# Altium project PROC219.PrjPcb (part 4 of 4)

## Sheet PROC219_Hardware.SchDoc
size 431 x 279 mm; Date: Not shown in title block; ApprovedBy: Not shown in title block; CheckedBy: Not shown in title block; Author: Not shown in title block; CompanyName: Not shown in title block; Engineer: Not shown in title block; Organization: Not shown in title block; Address1: Not shown in title block; Address2: Not shown in title block; Address3: Not shown in title block; Address4: Not shown in title block; DocumentNumber: 3; Revision: Use project parameter SCH_Rev; SheetNumber: 16; SheetTotal: 16; PageSetup: Record=PageOptions¦CenterHorizontal=True¦CenterVertical=True¦PrintScale=1.00¦XCorrection=1.00¦YCorrection=1.00¦PrintKind=0¦BorderSize=5000000¦LeftOffset=0¦BottomOffset=0¦Orientation=2¦PaperLength=1000¦PaperWidth=1000¦Scale=100¦PaperSource=15¦PrintQuality=600¦MediaType=1¦DitherType=10¦PaperKind=Letter¦PrintScaleMode=1
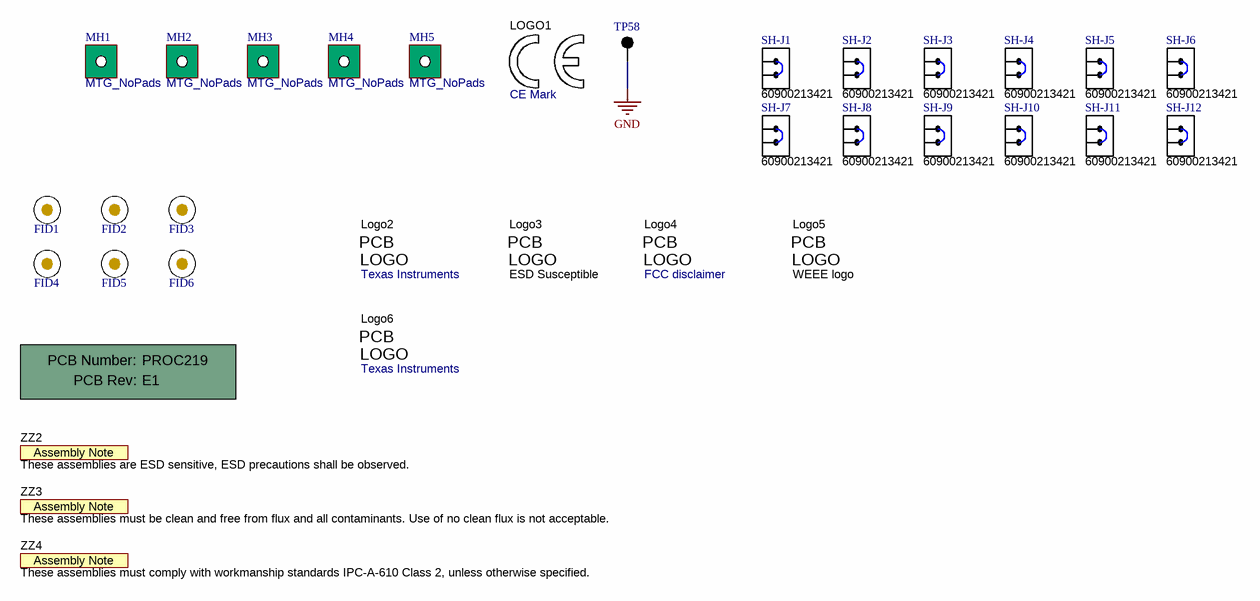
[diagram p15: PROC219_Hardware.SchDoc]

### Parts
!PCB1  Printed Circuit Board  (value not drawn)  (mechanical)
FID1  Fiducial  [Fiducial10-20]  (value not drawn)  (no BOM)
FID2  Fiducial  [Fiducial10-20]  (value not drawn)  (no BOM)
FID3  Fiducial  [Fiducial10-20]  (value not drawn)  (no BOM)
FID4  Fiducial  [Fiducial10-20]  (value not drawn)  (no BOM)
FID5  Fiducial  [Fiducial10-20]  (value not drawn)  (no BOM)
FID6  Fiducial  [Fiducial10-20]  (value not drawn)  (no BOM)
LOGO1  CE Mark  [CE_Mark_5mm]  (no BOM)
Logo2  Texas Instruments  [TI_Horizontal_Overlay_Medium]  (no BOM)
Logo3  ESD Susceptible  [ESD_Overlay_Large]  (no BOM)
Logo4  FCC disclaimer  [FCC_disclaimer]  (no BOM)
Logo5  WEEE logo  [WEEE_Minimum]  (no BOM)
Logo6  Texas Instruments  [TI_Horizontal_Overlay_Medium]  (no BOM)
MH1  MTG_NoPads  [NPTH125mil]  (no BOM)
MH2  MTG_NoPads  [NPTH125mil]  (no BOM)
MH3  MTG_NoPads  [NPTH125mil]  (no BOM)
MH4  MTG_NoPads  [NPTH125mil]  (no BOM)
MH5  MTG_NoPads  [NPTH125mil]  (no BOM)
SH-J1  60900213421  [Wurth_60900213421]
SH-J2  60900213421  [Wurth_60900213421]
SH-J3  60900213421  [Wurth_60900213421]
SH-J4  60900213421  [Wurth_60900213421]
SH-J5  60900213421  [Wurth_60900213421]
SH-J6  60900213421  [Wurth_60900213421]
SH-J7  60900213421  [Wurth_60900213421]
SH-J8  60900213421  [Wurth_60900213421]
SH-J9  60900213421  [Wurth_60900213421]
SH-J10  60900213421  [Wurth_60900213421]
SH-J11  60900213421  [Wurth_60900213421]
SH-J12  60900213421  [Wurth_60900213421]
TP58  5011  [Keystone5011]  (value not drawn)
ZZ2  These assemblies are ESD sensitive, ESD precautions shall be observed.  [AssemblyNote]  (no BOM)
ZZ3  These assemblies must be clean and free from flux and all contaminants. Use of no clean flux is not acceptable.  [AssemblyNote]  (no BOM)
ZZ4  These assemblies must comply with workmanship standards IPC-A-610 Class 2, unless otherwise specified.  [AssemblyNote]  (no BOM)

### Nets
GND: TP58.1

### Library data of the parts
!PCB1 = CMP-0003618-2: Manufacturer: Any; PartNumber: PROC219
FID1-FID6 = CMP-0077181-1: Fiducial mark.  There is nothing to buy or mount.
LOGO1 = CMP-0074844-1: SymbolCreator: a0412235
Logo2 Logo6 = CMP-0074838-1: Texas Instrument Corporate Signature; SymbolCreator: a0412235; Lib Reference: TI_Logo
Logo3 = CMP-0074840-1: ESD Susceptible Symbol; SymbolCreator: a0412235; Lib Reference: ESD_Susceptible
Logo4 = CMP-0074847-1: FCC_disclaimer
Logo5 = CMP-0074769-4: Manufacturer: Texas Instruments; CompType: IC; AEC Category: Q200
MH1-MH5 = CMP-0078424-2: PCB Mounting Hole, No Pad; Manufacturer: Any; Key: Mounting Hole (non-standard) No Pad
SH-J1-SH-J12 = CMP-0003761-2: Shunt, 2.54mm, Gold, Black; Manufacturer: Wurth Elektronik
TP58 = CMP-0055148-2: Test Point, Multipurpose, Black, TH; Manufacturer: Keystone Electronics; CNHeader: FALSE; ContactFinish: Silver; Green_REACh: Passed; Green_Lifecycle: Active; CT: TRUE
ZZ2 = CMP-0077236-1
ZZ3 = CMP-0077237-1
ZZ4 = CMP-0077238-1

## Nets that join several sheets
3.3V: PROC219_Power_IN_Dig (5 pins), PROC219_MSPM0 (9 pins), PROC219_PLC (19 pins), PROC219_Pilot_Interface (R60.2 R64.2 R66.2 SW1.5), PROC219_GBT (SW2.5), PROC219_CHAdeMO (6 pins), PROC219_PluckLock (7 pins), PROC219_Temp_Sense (R121.2 R122.2), PROC219_Serial (9 pins), PROC219_CAN (8 pins), PROC219_IO (6 pins), PROC219_XDS110_Debug (32 pins), PROC219_Connectors (7 pins)
5V: PROC219_Power_IN_Dig (7 pins), PROC219_Power_Analog (L7.1), PROC219_CAN (C135.1 C140.1 U21.3 U23.3), PROC219_IO (R145.1 R149.1), PROC219_Connectors (J26.5)
12V: PROC219_Power_IN_Dig (7 pins), PROC219_CHAdeMO (6 pins), PROC219_PluckLock (F1.2 J14.2), PROC219_IO (R148.2), PROC219_Connectors (J30.1)
+12V_EXT: PROC219_Power_IN_Dig (R3.2), PROC219_Connectors (J26.1 J26.2)
+12Va: PROC219_Power_Analog (7 pins), PROC219_Pilot_Interface (C90.2 R70.1 U10.6), PROC219_GBT (8 pins)
+14V_EXT: PROC219_Power_Analog (6 pins), PROC219_Connectors (J26.3)
-12Va: PROC219_Power_Analog (7 pins), PROC219_Pilot_Interface (C92.2 U10.2 U10.5)
-14V_EXT: PROC219_Power_Analog (5 pins), PROC219_Connectors (J26.4)
GND: PROC219_Power_IN_Dig (37 pins), PROC219_Power_Analog (26 pins), PROC219_MSPM0 (22 pins), PROC219_PLC (48 pins), PROC219_Pilot_Interface (15 pins), PROC219_GBT (21 pins), PROC219_CHAdeMO (24 pins), PROC219_PluckLock (22 pins), PROC219_Temp_Sense (D29.2 D30.2 J15.1 TP41.1), PROC219_Serial (19 pins), PROC219_CAN (22 pins), PROC219_IO (18 pins), PROC219_XDS110_Debug (36 pins), PROC219_Connectors (28 pins), PROC219_Hardware (TP58.1)
AM62L_GPIO_EV_PlugIN: PROC219_Pilot_Interface (SW1.7), PROC219_Connectors (J28.2)
AM62L_GPIO_GBT_EV_PlugIN: PROC219_GBT (SW2.7), PROC219_Connectors (J28.4)
AM62L_MSP_BSL: PROC219_MSPM0 (R38.2 U8.2), PROC219_Connectors (J28.14)
AM62L_MSP_~{RST}: PROC219_MSPM0 (Q4.1 R40.1), PROC219_Connectors (J28.10)
AM62L_RS232_RX: PROC219_Serial (R131.2 TP48.1), PROC219_Connectors (J28.13)
AM62L_RS232_TX: PROC219_Serial (R128.2 TP46.1), PROC219_Connectors (J27.8)
AM62L_RS485_DIR: PROC219_Serial (R127.2 U19.3 U19.4), PROC219_Connectors (J28.23)
AM62L_RS485_RX: PROC219_Serial (R126.2 TP43.1), PROC219_Connectors (J28.20)
AM62L_RS485_TX: PROC219_Serial (R125.2 TP42.1), PROC219_Connectors (J28.18)
AM62L_UART_RX: PROC219_MSPM0 (R31.1 R33.2), PROC219_Connectors (J27.10)
AM62L_UART_TX: PROC219_MSPM0 (R32.1 R34.2), PROC219_Connectors (J27.9)
CAN1_RX: PROC219_CAN (R135.1 U21.4), PROC219_Connectors (J28.15)
CAN1_TX: PROC219_CAN (R134.1 U21.1), PROC219_Connectors (J28.7)
CAN2_RX: PROC219_CAN (R141.1 U23.4), PROC219_Connectors (J29.2 U33.5)
CAN2_TX: PROC219_CAN (R140.1 U23.1), PROC219_Connectors (J29.1 U33.3)
MSP_ADC_CP: PROC219_MSPM0 (U7.31), PROC219_Pilot_Interface (6 pins)
MSP_ADC_GBT_DP1: PROC219_MSPM0 (U7.30), PROC219_GBT (C117.2 R78.1 R79.2 TP24.1)
MSP_ADC_IN_3: PROC219_MSPM0 (U7.10), PROC219_IO (U28.1 U28.4)
MSP_ADC_PP: PROC219_MSPM0 (U7.26), PROC219_Pilot_Interface (R67.2 TP22.1)
MSP_DEBUG_UART_RX: PROC219_MSPM0 (U7.55), PROC219_XDS110_Debug (J24.5 U31.3)
MSP_DEBUG_UART_TX: PROC219_MSPM0 (U7.54), PROC219_XDS110_Debug (J24.7 U31.1)
MSP_GPIO_CdM_d1: PROC219_MSPM0 (U7.19), PROC219_CHAdeMO (R88.1 R90.1)
MSP_GPIO_CdM_d2: PROC219_MSPM0 (U7.18), PROC219_CHAdeMO (Q13.3 R95.2)
MSP_GPIO_CdM_EV_CP: PROC219_MSPM0 (U7.16), PROC219_CHAdeMO (Q14.1 R101.1)
MSP_GPIO_CdM_j: PROC219_MSPM0 (U7.15), PROC219_CHAdeMO (R99.2 R100.2 TP27.1)
MSP_GPIO_CdM_PD: PROC219_MSPM0 (U7.14), PROC219_CHAdeMO (TP28.1 U15.1)
MSP_GPIO_EV_Charge: PROC219_MSPM0 (U7.3), PROC219_Pilot_Interface (Q6.1 R71.1)
MSP_GPIO_GBT_EV_S2: PROC219_MSPM0 (U7.20), PROC219_GBT (Q10.1 R86.1)
MSP_GPIO_GBT_EV_S2': PROC219_MSPM0 (U7.22), PROC219_GBT (Q11.1 R85.1)
MSP_GPIO_GBT_S0: PROC219_MSPM0 (U7.27), PROC219_GBT (R75.2 U11.4)
MSP_GPIO_GBT_S1: PROC219_MSPM0 (U7.23), PROC219_GBT (R76.2 U12.4)
MSP_GPIO_PL_CdM_FB: PROC219_MSPM0 (U7.21), PROC219_PluckLock (Q16.1 R119.2 TP35.1 U18.1)
MSP_GPIO_PL_DIR: PROC219_MSPM0 (U7.29), PROC219_PluckLock (TP33.1 U16.6)
MSP_GPIO_PL_nSLEEP: PROC219_MSPM0 (U7.28), PROC219_PluckLock (R110.1 TP31.1 U16.8)
MSP_IO_IN_1: PROC219_MSPM0 (U7.4), PROC219_IO (TP54.1 U25.4)
MSP_IO_IN_2: PROC219_MSPM0 (U7.6), PROC219_IO (TP56.1 U27.4)
MSP_IO_OUT_1: PROC219_MSPM0 (U7.5), PROC219_IO (U26.1)
MSP_IO_OUT_2: PROC219_MSPM0 (U7.1), PROC219_IO (U26.2 U26.3 U26.4)
MSP_IO_OUT_3: PROC219_MSPM0 (U7.60), PROC219_IO (U26.5 U26.6 U26.7)
MSP_PWM_CP: PROC219_MSPM0 (U7.62), PROC219_Pilot_Interface (TP20.1 U10.4)
MSP_PWM_PL_EN: PROC219_MSPM0 (U7.35), PROC219_PluckLock (TP32.1 U16.5)
MSP_PWM_R_ENABLE: PROC219_MSPM0 (U7.47), PROC219_Connectors (J26.9)
MSP_~{RST}: PROC219_MSPM0 (C49.1 Q4.3 R37.1 U7.38), PROC219_XDS110_Debug (J24.9 U31.5)
P_TEMP1: PROC219_MSPM0 (U7.9), PROC219_Temp_Sense (D30.1 J15.3 R122.1 TP40.1)
P_TEMP2: PROC219_MSPM0 (U7.8), PROC219_Temp_Sense (D29.1 J15.2 R121.1 TP39.1)
PA19_SWDIO: PROC219_MSPM0 (U7.12), PROC219_XDS110_Debug (J24.11 U31.4)
PA20_SWCLK: PROC219_MSPM0 (U7.13), PROC219_XDS110_Debug (D37.1 J24.13)
PL_FB: PROC219_MSPM0 (U7.25), PROC219_PluckLock (5 pins)
PLC_IRQ: PROC219_PLC (R44.1 R49.2 U9.73), PROC219_Connectors (J28.21)
PLC_N: PROC219_PLC (R54.1), PROC219_Pilot_Interface (C101.2 C102.2 L15.1)
PLC_nRST: PROC219_PLC (U9.29), PROC219_Connectors (J28.9)
PLC_P: PROC219_PLC (R52.1), PROC219_Pilot_Interface (C101.1 C102.1 L19.1)
PLC_SPI1_CLK: PROC219_PLC (U9.75), PROC219_Connectors (J28.27)
PLC_SPI1_CS0: PROC219_PLC (U9.77), PROC219_Connectors (J28.30)
PLC_SPI1_D0: PROC219_PLC (U9.79), PROC219_Connectors (J28.28)
PLC_SPI1_D1: PROC219_PLC (U9.78), PROC219_Connectors (J28.29)
PLC_SPI1_IRQ: PROC219_PLC (R42.1 R47.2 U9.74), PROC219_Connectors (J28.19)
PLC_ZC_IN: PROC219_PLC (U9.28), PROC219_Connectors (J26.15)
PW_EN_EXT: PROC219_Power_Analog (R27.1 U5.8 U5.10), PROC219_Connectors (J26.16)
R_MIRROR_OUT: PROC219_MSPM0 (U7.39), PROC219_Connectors (J26.12)
RCD_FAULT_SCL: PROC219_MSPM0 (U7.34), PROC219_Connectors (J30.3 R168.1 U35.4)
RCD_nFAULT: PROC219_MSPM0 (U7.48), PROC219_Connectors (J26.11 J31.3 U35.3)
RCD_RESET: PROC219_MSPM0 (U7.52), PROC219_Connectors (J31.1 U35.5)
RCD_TEST_SDA: PROC219_MSPM0 (U7.33), PROC219_Connectors (J31.2 R167.1 U35.1)
RELAY_CHECK: PROC219_MSPM0 (U7.44), PROC219_Connectors (J26.10)
Super_Cap_Char: PROC219_MSPM0 (U7.43), PROC219_Connectors (J26.18)
XDS_USB_N: PROC219_XDS110_Debug (U29.93), PROC219_Connectors (J25.A7 J25.B7 U32.3)
XDS_USB_P: PROC219_XDS110_Debug (U29.94), PROC219_Connectors (J25.A6 J25.B6 U32.5)
XDS_VBUS: PROC219_XDS110_Debug (R158.1), PROC219_Connectors (J25.A4-B9 J25.B4-A9 U32.1)

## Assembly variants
001: not fitted C59 C67 C91 FID1 FID2 FID3 L21 L22 R45 R47 R48 R49 R57 R112 R119 R132 R135 R141 R145 R149 R162 R167 R168 R169 R170 T2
